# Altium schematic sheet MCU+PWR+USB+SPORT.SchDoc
size A3; SheetNumber: 1; SheetTotal: 2
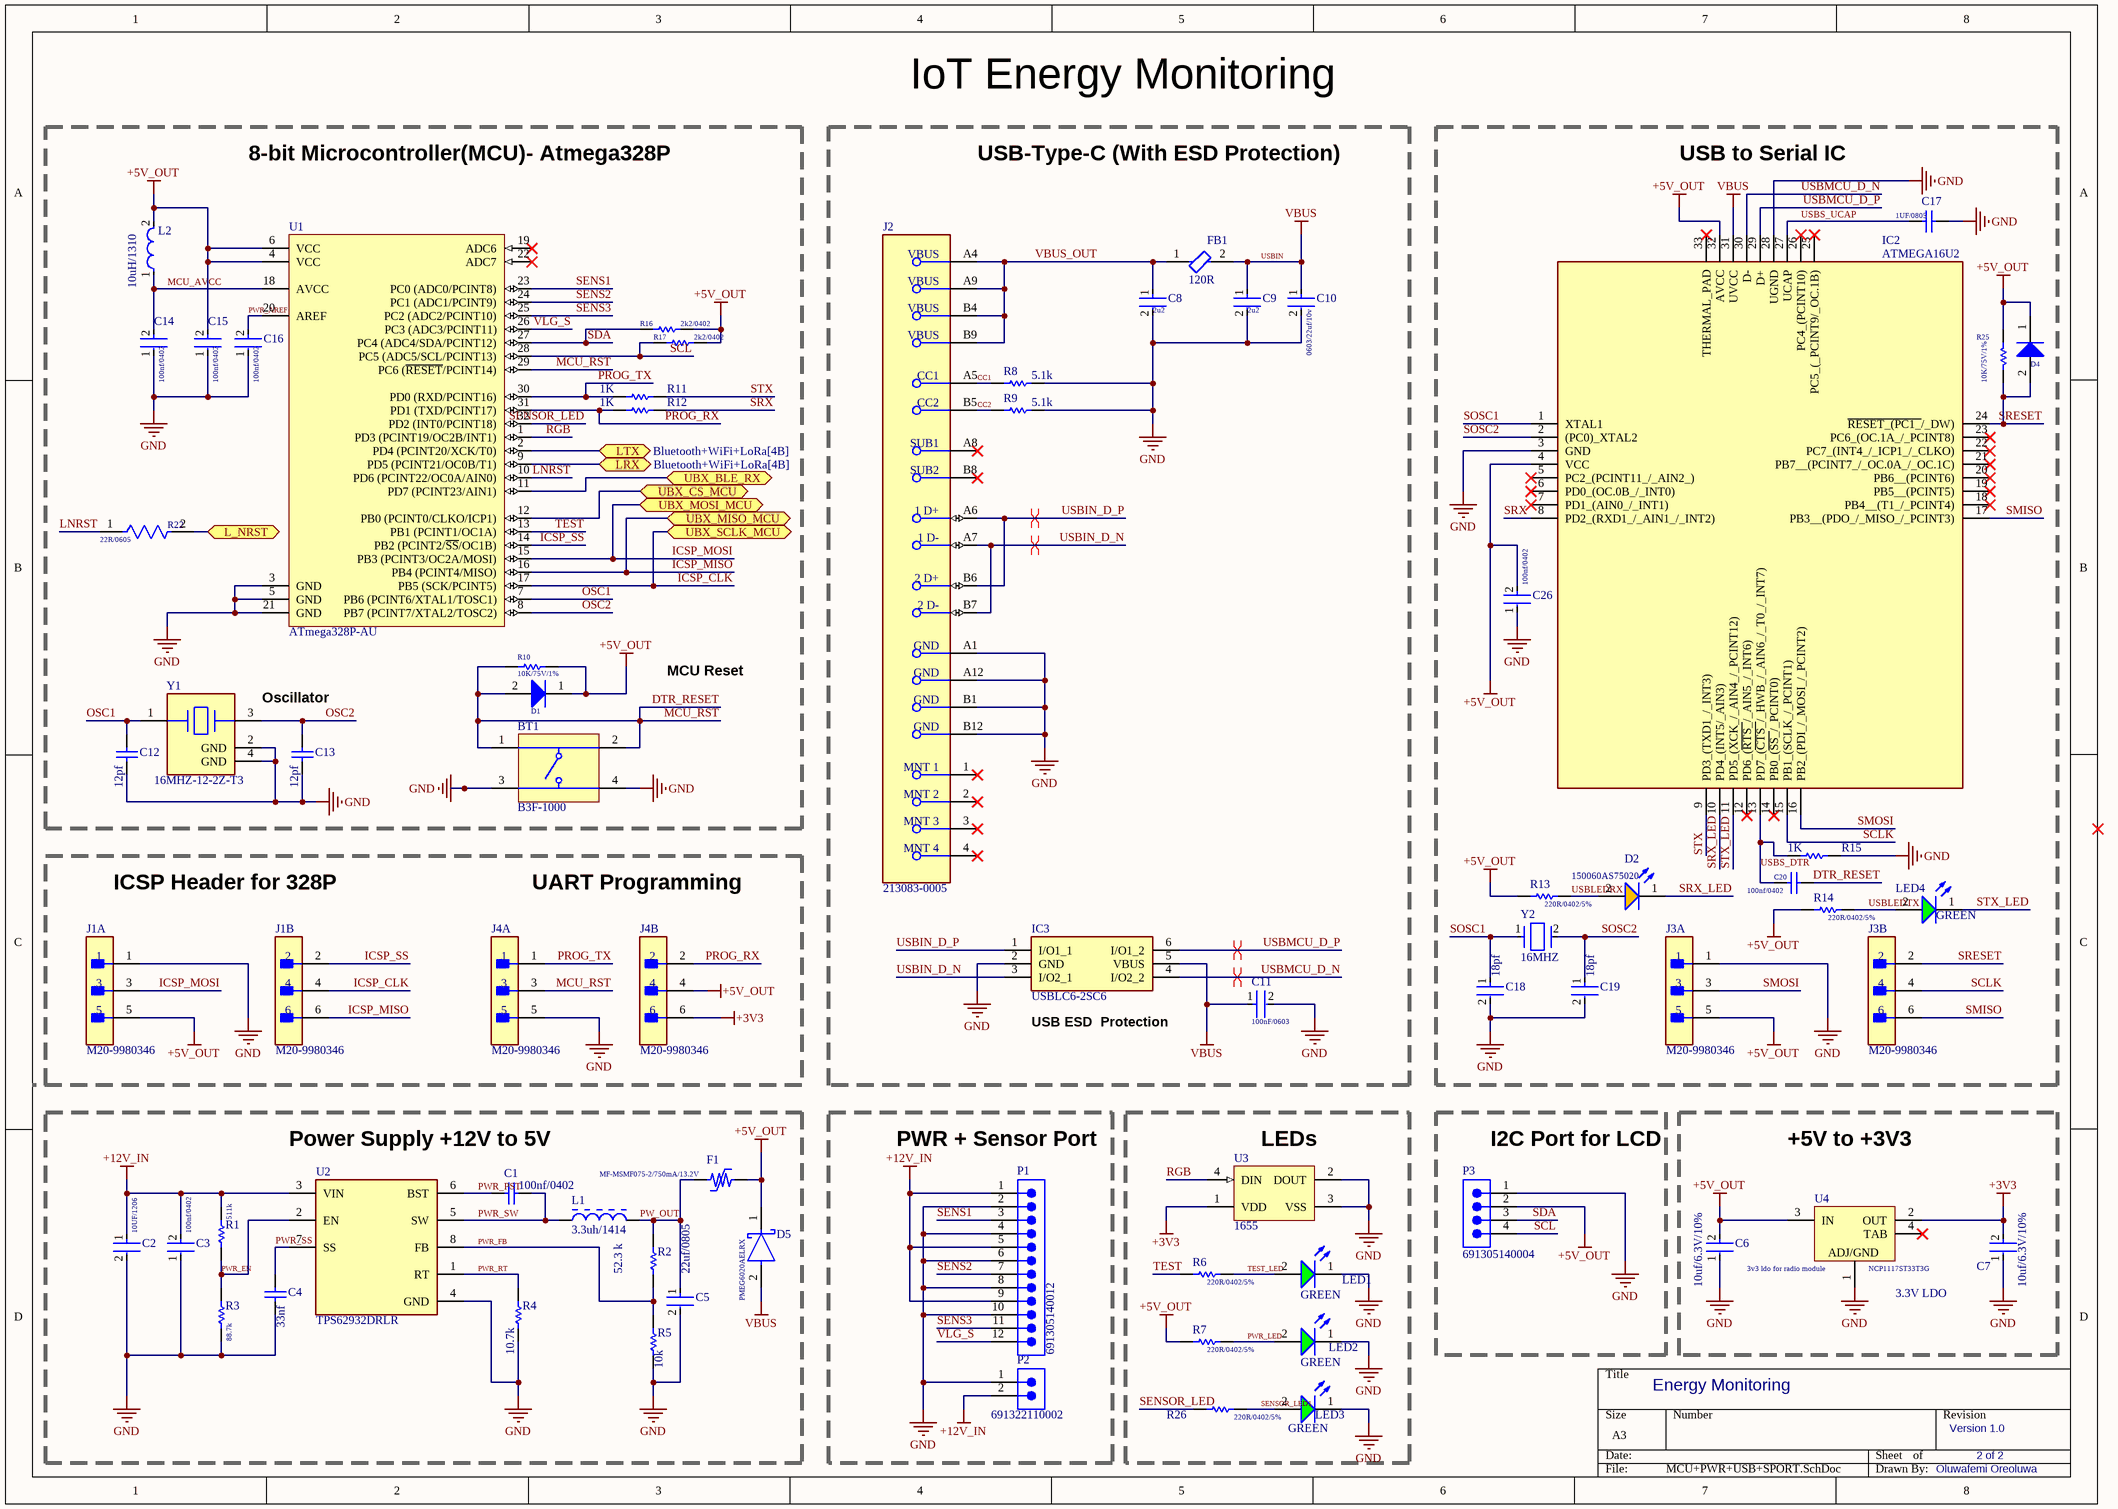
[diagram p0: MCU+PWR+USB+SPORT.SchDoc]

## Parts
BT1  B3F-1000  [OMRON-B3F-1000-4_V]
C1  100nf/0402  [CAPC1005X55X25LL05T10]
C2  10UF/1206  [FP-C3216-160-0_2-IPC_A]
C3  100nf/0402  [FP-GRM15-MFG]
C4  33nf  [CAPC1005X55X25NL05T10]
C5  22uf/0805  [FP-GRM21B-0_2-e0_2_0_7-IPC_C]
C6  10uf/6.3V/10%  [FP-C1608-080-0_1-IPC_B]
C7  10uf/6.3V/10%  [FP-C1608-080-0_1-IPC_B]
C8  2u2  [FP-GRM188-0_1-e0_2_0_5-MFG]
C9  2u2  [FP-GRM188-0_1-e0_2_0_5-MFG]
C10  0603/22uf/10v  [FP-GRM188-0_2-IPC_C]
C11  100nF/0603  [FP-CGA3E-0_3-0_1-IPC_A]
C12  12pf  [CAPC2013X94X50LL20T25]
C13  12pf  [CAPC2013X94X50LL20T25]
C14  100nf/0402  [FP-GRM15-MFG]
C15  100nf/0402  [FP-GRM15-MFG]
C16  100nf/0402  [FP-GRM15-MFG]
C17  1UF/0805  [CAPC2013X140X50LL20T25]
C18  18pf  [FP-C0805C-DN-MFG]
C19  18pf  [FP-C0805C-DN-MFG]
C20  100nf/0402  [CAPC1005X55X25LL05T10]
C26  100nf/0402  [FP-GRM15-MFG]
D1  BAT54HT1G/30V/2A  [ONSC-SOD-323-2-477-02_V]  (value not drawn)
D2  150060AS75020  [WL-SMCW_0603_150060xx75020]
D4  BAT54HT1G/30V/2A  [ONSC-SOD-323-2-477-02_V]  (value not drawn)
D5  PMEG6020AELRX  [FP-SOD123W-MFG]
F1  MF-MSMF075-2/750mA/13.2V  [BOUR-MF-MSMF050-2_V]
FB1  120R  [FP-BLM18-0_15-t0_8-IPC_A]
IC2  ATMEGA16U2  [QFN50P500X500X100-33N-D]
IC3  USBLC6-2SC6  [SOT95P280X145-6N]
J1  M20-9980346  [FP-M20-9980346-MFG]  (parts A,B of 2)
J2  213083-0005  [FP-2130830005-MFG]
J3  M20-9980346  [FP-M20-9980346-MFG]  (parts A,B of 2)
J4  M20-9980346  [FP-M20-9980346-MFG]  (parts A,B of 2)
L1  3.3uh/1414  [BOUR-SRN3015-2_V]
L2  10uH/1310  [FP-CB3225-IPC_A]
LED1  GREEN  [WL-SMCW_0603_150060xx75000]
LED2  GREEN  [WL-SMCW_0603_150060xx75000]
LED3  GREEN  [WL-SMCW_0603_150060xx75000]
LED4  GREEN  [WL-SMCW_0603_150060xx75000]
P1  691305140012  [691305140012]
P2  691322110002  [691322110002]
P3  691305140004  [691305140004]
R1  511k  [RESC1005X40X25NL05T05]
R2  52.3 k  [RESC1005X40X25LL05T05]
R3  88.7k  [RESC1005X40X25NL05T05]
R4  10.7k  [RESC1005X40X25NL05T05]
R5  10k  [RESC1609X50X30NL8T20]
R6  220R/0402/5%  [RESC1005X40X25LL05T05]
R7  220R/0402/5%  [RESC1005X40X25LL05T05]
R8  5.1k  [RESC0805(2012)_N]
R9  5.1k  [RESC0805(2012)_N]
R10  10K/75V/1%  [RESC1609X50X30NL8T20]
R11  1K  [RESC3216X70X50LL05T20]
R12  1K  [RESC3216X70X50LL05T20]
R13  220R/0402/5%  [RESC1005X40X25LL05T05]
R14  220R/0402/5%  [RESC1005X40X25LL05T05]
R15  1K  [RESC3216X70X50LL05T20]
R16  2k2/0402  [RESC1005X40X25NL5T10]
R17  2k2/0402  [RESC1005X40X25NL5T10]
R22  22R/0605  [FP-CPF0603-MFG]
R25  10K/75V/1%  [RESC1609X50X30NL8T20]
R26  220R/0402/5%  [RESC1005X40X25LL05T05]
U1  ATmega328P-AU  [32A_M]
U2  TPS62932DRLR  [FP-DRL0008A-MFG]
U3  1655  [ADA-RGB-1655_V]
U4  NCP1117ST33T3G  [ONSC-SOT-223-4-318H-01_A_V]
Y1  16MHZ-12-2Z-T3  [FP-ABM8AIG-MFG]
Y2  16MHZ  [FP-ABM7-MFG]

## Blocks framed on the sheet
8-bit Microcontroller(MCU)- Atmega328P: BT1 C12-C16 D1 L2 R10-R12 R16 R17 R22 U1 Y1
USB-Type-C (With ESD Protection): C8-C11 FB1 IC3 J2 R8 R9
USB to Serial IC: C17-C20 C26 D2 D4 IC2 J3 LED4 R13-R15 R25 Y2
Power Supply +12V to 5V: C1-C5 D5 F1 L1 R1-R5 U2
PWR + Sensor Port: P1 P2
LEDs: LED1-LED3 R6 R7 R26 U3
I2C Port for LCD: P3
+5V to +3V3: C6 C7 U4

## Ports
L_NRST (bidir, see Bluetooth+WiFi+LoRa[4B]), LRX (bidir, see Bluetooth+WiFi+LoRa[4B]), LTX (bidir, see Bluetooth+WiFi+LoRa[4B]), UBX_BLE_RX (bidir, see Bluetooth+WiFi+LoRa[4B]), UBX_CS_MCU (bidir, see Bluetooth+WiFi+LoRa[4B]), UBX_MISO_MCU (bidir, see Bluetooth+WiFi+LoRa[4B]), UBX_MOSI_MCU (bidir, see Bluetooth+WiFi+LoRa[4B]), UBX_SCLK_MCU (bidir, see Bluetooth+WiFi+LoRa[4B])

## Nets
+3V3: C7.2 J4.6 U3.1(VDD) U4.2(OUT)
+5V_OUT: C6.2 C15.2 C26.2 D1.1(K) D4.1(K) D5.1(C) F1.2 IC2.4(VCC) IC2.32(AVCC) J1.5 J3.5 J4.4 L2.2 P3.2 R7.1 R10.1 R13.1 R14.1 R16.1 R17.1 R25.1 U1.4(VCC) U1.6(VCC) U4.3(IN)
+12V_IN: C2.1 C3.2 P1.1 P1.5 P1.9 P2.2 R1.2 U2.3(VIN)
GND: BT1.3 BT1.4 C2.2 C3.1 C4.1 C5.2 C6.1 C7.1 C8.2 C9.2 C10.2 C11.2 C12.1 C13.1 C14.1 C15.1 C16.1 C17.2 C18.2 C19.2 C26.1 IC2.3(GND) IC2.28(UGND) IC3.2(GND) J1.1 J2.A1(GND) J2.A12(GND) J2.B1(GND) J2.B12(GND) J3.1 J4.5 LED1.1(K) LED2.1(K) LED3.1(K) P1.2 P1.4 P1.6 P1.8 P1.10 P2.1 P3.1 R3.1 R4.1 R5.1 R8.1 R9.1 R15.2 U1.3(GND) U1.5(GND) U1.21(GND) U2.4(GND) U3.2(DOUT) U3.3(VSS) U4.1(ADJ/GND) Y1.2(GND) Y1.4(GND)
USBIN: C9.1 C10.1 C11.1 D5.2(A) FB1.2 IC2.31(UVCC) IC3.5(VBUS)  [also labelled VBUS]
CC1: J2.A5(CC1) R8.2
CC2: J2.B5(CC2) R9.2
DTR_RESET: BT1.1 BT1.2 C20.2 D1.2(A) J4.3 R10.2 U1.29(PC6_(~{RESET}/PCINT14))  [also labelled MCU_RST]
ICSP_CLK: J1.4 U1.17(PB5_(SCK/PCINT5)) ; port UBX_SCLK_MCU
ICSP_MISO: J1.6 U1.16(PB4_(PCINT4/MISO)) ; port UBX_MISO_MCU
ICSP_MOSI: J1.3 U1.15(PB3_(PCINT3/OC2A/MOSI)) ; port UBX_MOSI_MCU
ICSP_SS: J1.2 U1.14(PB2_(PCINT2/~{SS}/OC1B))
L_NRST: R22.2 ; port L_NRST
LNRST: R22.1 U1.10(PD6_(PCINT22/OC0A/AIN0))
LRX: U1.9(PD5_(PCINT21/OC0B/T1)) ; port LRX
LTX: U1.2(PD4_(PCINT20/XCK/T0)) ; port LTX
MCU_AVCC: C14.2 L2.1 U1.18(AVCC)
OSC1: C12.2 U1.7(PB6_(PCINT6/XTAL1/TOSC1)) Y1.1
OSC2: C13.2 U1.8(PB7_(PCINT7/XTAL2/TOSC2)) Y1.3
PROG_RX: J4.2 R12.1 U1.31(PD1_(TXD/PCINT17))
PROG_TX: J4.1 R11.1 U1.30(PD0_(RXD/PCINT16))
PW_OUT: C5.1 F1.1 L1.2 R2.2
PWR_AREF: C16.2 U1.20(AREF)
PWR_EN: R1.1 R3.2 U2.2(EN)
PWR_FB: R2.1 R5.2 U2.8(FB)
PWR_LED: LED2.2(A) R7.2
PWR_PST: C1.1 U2.6(BST)
PWR_RT: R4.2 U2.1(RT)
PWR_SS: C4.2 U2.7(SS)
PWR_SW: C1.2 L1.1 U2.5(SW)
RGB: U1.1(PD3_(PCINT19/OC2B/INT1)) U3.4(DIN)
SCL: P3.4 R17.2 U1.28(PC5_(ADC5/SCL/PCINT13))
SCLK: IC2.15(PB1_(SCLK_/_PCINT1)) J3.4
SDA: P3.3 R16.2 U1.27(PC4_(ADC4/SDA/PCINT12))
SENS1: P1.3 U1.23(PC0_(ADC0/PCINT8))
SENS2: P1.7 U1.24(PC1_(ADC1/PCINT9))
SENS3: P1.11 U1.25(PC2_(ADC2/PCINT10))
SENSOR_LED: R26.1 U1.32(PD2_(INT0/PCINT18))
SENSOR_LED1: LED3.2(A) R26.2
SMISO: IC2.17(PB3__(PDO_/_MISO_/_PCINT3)) J3.6
SMOSI: IC2.16(PB2_(PDI_/_MOSI_/_PCINT2)) J3.3
SOSC1: C18.1 IC2.1(XTAL1) Y2.1
SOSC2: C19.1 IC2.2((PC0)_XTAL2) Y2.2
SRESET: D4.2(A) IC2.24(~{RESET_(PC1_}/_DW)) J3.2 R25.2
SRX: IC2.8(PD2_(RXD1_/_AIN1_/_INT2)) R12.2
SRX_LED: D2.1(K) IC2.10(PD4_(INT5/_AIN3))
STX: IC2.9(PD3_(TXD1_/_INT3)) R11.2
STX_LED: IC2.11(PD5_(XCK_/_AIN4_/_PCINT12)) LED4.1(K)
TEST: R6.1 U1.13(PB1_(PCINT1/OC1A))
TEST_LED: LED1.2(A) R6.2
UBX_BLE_RX: U1.11(PD7_(PCINT23/AIN1)) ; port UBX_BLE_RX
UBX_CS_MCU: U1.12(PB0_(PCINT0/CLKO/ICP1)) ; port UBX_CS_MCU
USBIN_D_N: IC3.3(I/O2_1) J2.A7(1_D-) J2.B7(2_D-)
USBIN_D_P: IC3.1(I/O1_1) J2.A6(1_D+) J2.B6(2_D+)
USBLEDRX: D2.2(A) R13.2
USBLEDTX: LED4.2(A) R14.2
USBMCU_D_N: IC2.30(D-) IC3.4(I/O2_2)
USBMCU_D_P: IC2.29(D+) IC3.6(I/O1_2)
USBS_DTR: C20.1 IC2.13(PD7_(~{CTS_}/_HWB_/_AIN6_/_T0_/_INT7)) R15.1
USBS_UCAP: C17.1 IC2.27(UCAP)
VBUS_OUT: C8.1 FB1.1 J2.A4(VBUS) J2.A9(VBUS) J2.B4(VBUS) J2.B9(VBUS)
VLG_S: P1.12 U1.26(PC3_(ADC3/PCINT11))

Not connected (* = marked no-connect by the designer): IC2 5(PC2_(PCINT11_/_AIN2_))* 6(PD0_(OC.0B_/_INT0))* 7(PD1_(AIN0_/_INT1))* 12(PD6_(~{RTS_}/_AIN5_/_INT6))* 14(PB0_(~{SS_}/_PCINT0))* 18(PB4__(T1_/_PCINT4))* 19(PB5__(PCINT5))* 20(PB6__(PCINT6))* 21(PB7__(PCINT7_/_OC.0A_/_OC.1C))* 22(PC7_(INT4_/_ICP1_/_CLKO))* 23(PC6_(OC.1A_/_PCINT8))* 25(PC5_(_PCINT9/_OC.1B))* 26(PC4_(PCINT10))* 33(THERMAL_PAD)*; J2 1(MNT_1)* 2(MNT_2)* 3(MNT_3)* 4(MNT_4)* A8(SUB1)* B8(SUB2)*; U1 19(ADC6)* 22(ADC7)*; U4 4(TAB)*

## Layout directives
differential pair; differential pair class DIF_USB: USBIN_D_N, USBIN_D_P, USBMCU_D_N, USBMCU_D_P

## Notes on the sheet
- IoT Energy Monitoring
- Oscillator
- MCU Reset
- ICSP Header for 328P
- UART Programming
- (near IC3) USB ESD  Protection
- (near U4) 3v3 ldo for radio module
- (near U4) 3.3V LDO
- Energy Monitoring
- Version 1.0
- 2 of 2
- Oluwafemi Oreoluwa

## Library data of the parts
BT1 = CMP-1677-00002-1: Tactile Switch, SPST-NO, 0.05 A, 5 to 24 V, -25 to 70 degC, 4-Pin THD, RoHS, Bulk; Shielding: Shielded; Gender: Female; Capacitance: -45 f; Voltage Rating: 150 V; Current Rating: 1.5 A
C1 C20 = CMP-2000-06331-1: Chip Capacitor, 0.1 uF, +/- 10%, 10 V, -55 to 125 degC, 0402 (1005 Metric), RoHS, Tape and Reel; Manufacturer: Murata; Rated Voltage: 10V; Capacitance: 100000pF; Dielectric: X7R
C2 = CMP-2000-06045-2: Multilayer Ceramic Capacitors 10uF ±10% 50V X5R SMD 1206
C3 C14-C16 C26 = CMP-2100-03641-2: CAP CER 0.1UF 16V X7R 0402; Manufacturer Part Number: GRM155R71C104KA88D; Manufacturer: Murata; Standoff Height: 0mm; Tolerance: 10%; Voltage Rating: 16Vdc; Material: Ceramic; Capacitance: 0.10μF; Value: 0.10μF
C4 = CMP-2008-04594-1: Part Number: GRM155R71A333KA01D; Manufacturer: Murata
C5 = CMP-06035-039918-1: Chip Multilayer Ceramic Capacitors for General Purpose, 0805, 22uF, X5R, 15%, 20%, 10V; Dissipation Factor: 0.035%
C6 C7 = CMP-08246-005333-1: Multilayer Ceramic Capacitors 10μF ±10% 6.3V X5R SMD 0603; Capacitance: 10uF
C8 C9 = CMP-2006-02836-2: Chip Multilayer Ceramic Capacitors for General Purpose, 0603, 2.2uF, X7R, 15%, 10%, 10V
C10 = CMP-2000-06337-3: Chip Multilayer Ceramic Capacitors for General Purpose, 0603, 22uF, X5R, 15%, 20%, 10V
C11 = CMP-2000-07546-2: Cap Ceramic 100nF 50V X7R 10% Pad SMD 0603 +125°C Automotive T/R
C12 C13 = CMP-2007-04128-1: Part Number: 08051A120JAT2A; Manufacturer: AVX Interconnect / Elco
C17 = CMP-2007-03234-1: Part Number: C0805C105K3RACTU; Manufacturer: Kemet
C18 C19 = CMP-2007-00302-2: CAP CER 18PF 50V C0G/NP0 0805; Manufacturer: KEMET; Manufacturer Part Number: C0805C180J5GACTU; Temperature Characteristic: C0G; Tolerance: 0.05; Material: Ceramic; Temperature Coefficient: 30ppm/°C
D1 D4 = CMP-1055-00462-1: Schottky Barrier Diode, 2-Pin SOD-323, Pb-Free, Tape and Reel; Manufacturer: On Semiconductor; Configuration: Single; trr Max (ns): 5; IFSM Max (A): 0.6
D2 = CMP-03913-104891423-2: WL-SMCW SMT Mono-Color Chip LED Waterclear super f; Luminous Intensity: 140mcd; Max Reverse Voltage (DC): 5V; Peak Wavelength: 610nm; Forward Current: 60mA; Viewing Angle: 140°; Forward Voltage: 2V; Dominant Wavelength: 605nm
D5 = CMP-14398-000040-1: DIODE SCHOTTKY 60V 2A CFP3
F1 = CMP-2100-03654-1: PTC Resettable Fuse, 13.2 V, 750 mA, -40 to 85 degC, 2-Pin SMD, RoHS, Tape and Reel; Manufacturer: Bourns; Voltage Rating: 13.2V; Resistance: 450mOhm; Max Current Rating: 100A; Power Dissipation: 800mW
FB1 = CMP-0686-00557-7: Chip Ferrite Bead, 0603, 120Ω @ 100MHz, 0.05Ω, 25%, 2A; Number of Circuits: 1; Shielding: Unshielded; Material: Steel; DC Resistance (DCR): 50mR
IC2 = ATMEGA16U2: Integrated Circuit; Manufacturer_Name: Microchip
IC3 = USBLC6-2SC6: Integrated Circuit; Manufacturer_Name: STMicroelectronics
J1 J3 J4 = CMP-2000-06636-2: CONN HEADER VERT 6POS 2.54MM; Manufacturer: Harwin; Current Rating: 3A; Number Of Contacts: 6; Conn Gender: Male; Conn Orientation: Vertical
J2 = CMP-04767-000030-2: CONN RCP USB2.0 TYP C 24P SMD RA; NexarPartId: 114105384; Current Rating: 5A; Number of Contacts: 16; Voltage Rating: 30V; Gender: Receptacle
L1 = CMP-0007-00001-1: Semi-shielded Power Inductor, 3.3 uH, +/- 20%, 1.6 A, -40 to 125 degC, 3 x 3 x 1.5 mm SMD, RoHS and Halogen Free, Tape and Reel; Manufacturer: Bourns; PartNumber: SRN3015-3R3M; DCR Max: 0.112 Ohm; Resistance to Solder Heat: +260 degC for 10 sec.; Inductance: 3.3 uH; Rated current: 1.6 A; SRF Min: 75 MHz; Isat: 1.4 A; Inductance tolerance: +/- 20%
L2 = CMP-14484-000123-1: SMD Inductors 10uH ±20% 0.9A 0.1729Ω 1210; Shielding: Unshielded; DC Resistance (DCR): 172.9mR; Core Material: Ferrite; Self Resonant Frequency: 23MHz; Max DC Current: 900mA; Test Frequency: 100kHz
LED1-LED4 = CMP-1426-00006-6: NexarPartId: 29717778; Reverse Voltage: 5V; Forward Voltage: 2V; Viewing Angle: 140°; Luminous Intensity: 40mcd; Test Current: 20mA; Max Junction Temperature (Tj): 95°C; Wavelength: 570nm; Forward Current: 100mA; Lens Style: Clear, Rectangular; Power Dissipation: 72mW; Peak Wavelength: 572nm
P1 = CMP-1502-01782-2: NexarPartId: 105952413
P2 = CMP-1502-01791-3: NexarPartId: 18818346; Voltage Rating: 300V; Number of Contacts: 2; Gender: Male; Current: 10A; Number of Levels: 1; Pitch: 3.5052mm
P3 = CMP-1502-01777-2: NexarPartId: 78871379; Gender: Male
R1 = CMP-2002-00076-1: Manufacturer: Vishay Dale; Part Number: CRCW0402511KFKED
R2 = CMP-2002-00086-1: Part Number: CRCW040252K3FKED; Manufacturer: Vishay Dale
R3 = CMP-2002-00251-1: Manufacturer: Vishay Dale; Part Number: CRCW040288K7FKED
R4 = CMP-1011-00626-2: Manufacturer: Vishay Dale; Part Number: CRCW040210K7FKED
R5 R10 R25 = CMP-1666-00005-4: Chip Resistor, 10 KOhm, +/- 1%, 100 mW, -55 to 155 degC, 0603 (1608 Metric), RoHS, Tape and Reel; Manufacturer: Vishay Semiconductor; Voltage Rating: 75 V
R6 R7 R13 R14 R26 = CMP-2002-00487-3: Chip Resistor, 220 Ohm, +/- 5%, 100 mW, -55 to 155 degC, 0402 (1005 Metric), RoHS, Tape and Reel; Manufacturer: Basic Passives; PartNumber: ERJ-2GEJ221X; Voltage Rating: 50 V; Case\/Package: 0402; Power Rating: 100 mW; Resistance: 220 Ohm
R8 R9 = CMP-1013-00591-1: 5K11 0.125W 1% 0805 (2012 Metric)  SMD; Case-Metric: 2012; Value: 5110.00 Ohm; Case-EIA: 0805
R11 R12 R15 = CMP-2003-00017-1: Manufacturer: Panasonic; Part Number: ERJ-8ENF1001V
R16 R17 = CMP-2002-07969-2: Chip Resistor, 2.2 KOhm, +/- 5%, 0.063 W, -55 to 155 degC, 0402 (1005 Metric), RoHS, Tape and Reel; Voltage Rating (DC): 50 V; Case\Package: 0402; Power Rating: 63 mW
R22 = CMP-03211-007811-1: RES SMD 22Ω 0.1% 1/16W 0603; Manufacturer: TE Connectivity; Manufacturer Part Number: CPF0603B22RE1; Temperature Coefficient: 25ppm/°C; Power Rating: 0.063W; Voltage Rating: 50V
U1 = CMP-0095-00269-2: 8-bit AVR Microcontroller, 32KB Flash, 1KB EEPROM, 2KB SRAM, 32-pin TQFP, Industrial Grade (-40°C to 85°C)
U2 = CMP-04918-000714-1: 3.8-V TO 30-V INPUT, 2-A, 200-KH
U3 = CMP-2000-05026-1: Intelligent Control LED Integrated Light Source, 3.5 to 5.3 V, -25 to 80 degC, 4-Pin SMD, RoHS, Tape and Reel; Manufacturer: Adafruit-Industries-LLC; Number of LEDs: 10; Configuration: Discrete; Utilized LED: WS2812(5050)
U4 = CMP-1679-00010-1: Low-Dropout Positive Fixed Voltage Regulator, 1 A, 3.3 V Output Voltage, 0 to 125 degC, 4-Pin SOT-223 (318H-01), Pb-Free, Tape and Reel; Resistance: 220 kohm; Type (Resistor): Thick Film; Voltage Rating: 75 V; Tolerance: 1%; Case\Package: 0603; Power Rating: 100 mW
Y1 = CMP-27762-000014-2: Crystal 16MHz ±20ppm (Tol) ±50ppm (Stability) 12pF FUND 70Ω Automotive 4-Pin Ultra Mini-CSMD T/R; ESR (Equivalent Series Resistance): 70R
Y2 = CMP-27762-000095-1: Crystal 16MHz ±20ppm 18pF SMD-2 6mm x 3.5mm; ESR (Equivalent Series Resistance): 50R; Frequency Stability: 30ppm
